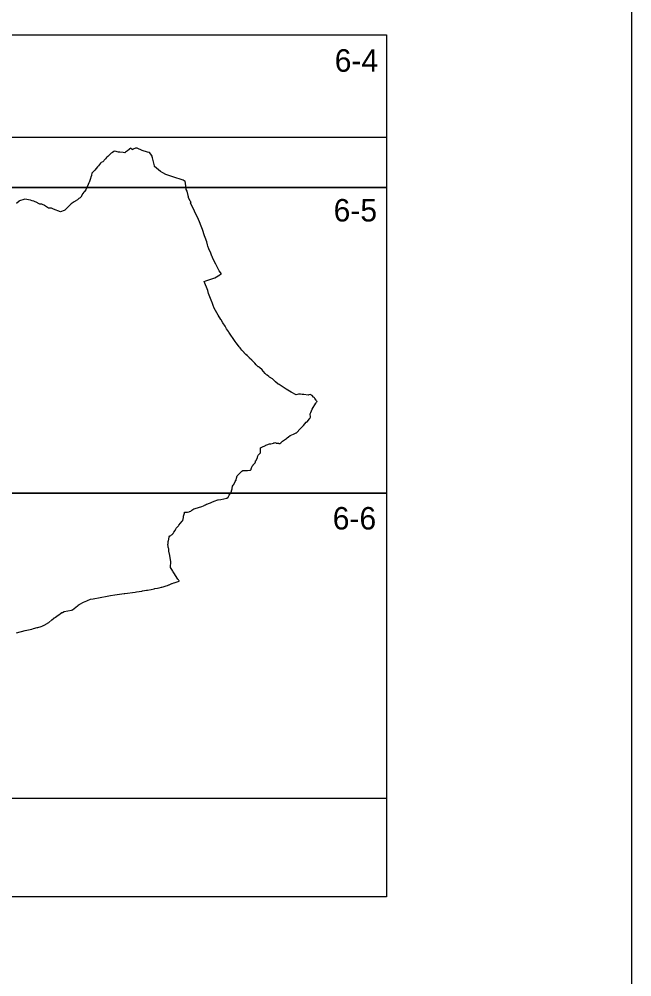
# Model space of a CAD drawing. Extents: x -447352 to -425530, y -1135906 to -1125104.
# Drawn here: x -443174.5 to -442923.9, y -1126663.9 to -1126271.9 of the extents above; entities that cross this region are included whole.
import ezdxf

# ---------------------------------------------------------------- set-up
doc = ezdxf.new("R2010")
doc.units = 0
for name, color, linetype in [('Vrstva 1', 7, 'Continuous'), ('Vrstva 10', 7, 'Continuous'), ('Vrstva 4', 7, 'Continuous')]:
    doc.layers.add(name, color=color, linetype=linetype)

msp = doc.modelspace()

# ---------------------------------------------------------------- linework, layer by layer
at = {"layer": 'Vrstva 1'}
msp.add_lwpolyline([(-444408.89, -1126016.81), (-444408.89, -1127066.81), (-442923.89, -1127066.81), (-442923.89, -1126016.81)], close=True, dxfattribs=at)
msp.add_lwpolyline([(-443175.6, -1126523.09), (-443172.06, -1126522.22), (-443169.29, -1126521.55), (-443168.62, -1126521.34), (-443167.13, -1126520.98), (-443166.92, -1126520.92), (-443165.49, -1126520.53), (-443164.89, -1126520.27), (-443164.67, -1126520.17), (-443164.51, -1126520.11), (-443163.69, -1126519.66), (-443163.63, -1126519.62), (-443162.32, -1126518.84), (-443161.17, -1126517.79), (-443160.52, -1126517.29), (-443160.39, -1126517.18), (-443160.37, -1126517.17), (-443160.21, -1126517.04), (-443160.06, -1126516.94), (-443159.26, -1126516.38), (-443159.2, -1126516.34), (-443159.13, -1126516.29), (-443158.62, -1126515.94), (-443158.25, -1126515.68), (-443157.59, -1126515.22), (-443157, -1126514.81), (-443156.84, -1126514.84), (-443156.83, -1126514.84), (-443156.81, -1126514.82), (-443156.08, -1126514.43), (-443153.12, -1126513.85), (-443152.7, -1126513.7), (-443150.67, -1126512.07), (-443150.2, -1126511.73), (-443150.17, -1126511.71), (-443149.81, -1126511.45), (-443149.63, -1126511.33), (-443148.24, -1126510.63), (-443146.83, -1126509.99), (-443146.53, -1126509.84), (-443145.27, -1126509.38), (-443144.27, -1126509.13), (-443138.56, -1126508.07), (-443137.14, -1126507.81), (-443135.43, -1126507.56), (-443131.56, -1126506.99), (-443131.32, -1126506.96), (-443127.02, -1126506.44), (-443126.49, -1126506.38), (-443124.34, -1126506.02), (-443124.02, -1126505.97), (-443122.36, -1126505.7), (-443121.96, -1126505.63), (-443120.55, -1126505.34), (-443119.26, -1126505.07), (-443119.05, -1126505.03), (-443117.88, -1126504.8), (-443117.21, -1126504.67), (-443117.19, -1126504.67), (-443116.28, -1126504.46), (-443116.21, -1126504.44), (-443115.56, -1126504.28), (-443115.21, -1126504.17), (-443114.32, -1126503.88), (-443113.88, -1126503.73), (-443113.23, -1126503.49), (-443113.11, -1126503.45), (-443112.02, -1126502.96), (-443112.02, -1126502.96), (-443111.9, -1126502.92), (-443111.25, -1126502.69), (-443111.16, -1126502.66), (-443110.73, -1126502.5), (-443109.07, -1126501.92), (-443109.09, -1126501.87), (-443109.2, -1126501.7), (-443109.36, -1126501.47), (-443109.58, -1126501.15), (-443111.28, -1126498.51), (-443111.49, -1126498.16), (-443111.66, -1126497.89), (-443112.1, -1126497.18), (-443112.63, -1126496.33), (-443112.47, -1126493.97), (-443112.46, -1126493.88), (-443112.85, -1126491.58), (-443112.85, -1126491.56), (-443112.86, -1126491.54), (-443112.86, -1126491.54), (-443112.86, -1126491.51), (-443113.27, -1126489.68), (-443113.28, -1126489.49), (-443113.34, -1126488.69), (-443113.44, -1126488.41), (-443113.45, -1126488.39), (-443113.56, -1126488.17), (-443113.6, -1126488.09), (-443113.61, -1126487.71), (-443113.64, -1126487.01), (-443113.59, -1126486.52), (-443113.59, -1126486.5), (-443113.5, -1126485.64), (-443113.48, -1126485.53), (-443113.19, -1126483.89), (-443113.11, -1126483.81), (-443112.81, -1126483.47), (-443112.75, -1126483.4), (-443112.49, -1126483.28), (-443112.43, -1126483.22), (-443112.17, -1126483.02), (-443111.94, -1126482.84), (-443111.73, -1126482.68), (-443111.67, -1126482.64), (-443111.59, -1126482.51), (-443111.51, -1126482.39), (-443111.4, -1126482.22), (-443111.18, -1126481.89), (-443110.76, -1126481.24), (-443110.63, -1126480.99), (-443110.62, -1126480.98), (-443110.48, -1126480.69), (-443110.43, -1126480.6), (-443110.25, -1126480.27), (-443110.11, -1126480.12), (-443109.81, -1126479.81), (-443109.64, -1126479.63), (-443109.36, -1126479.28), (-443109.23, -1126479.11), (-443108.54, -1126478.26), (-443107.88, -1126477.45), (-443107.59, -1126477.09), (-443107.35, -1126475.92), (-443107.29, -1126475.69), (-443107.22, -1126475.41), (-443106.9, -1126474.1), (-443106.82, -1126473.82), (-443106.82, -1126473.79), (-443106.8, -1126473.74), (-443106.64, -1126473.73), (-443106.62, -1126473.73), (-443106.38, -1126473.73), (-443105.69, -1126473.71), (-443105.68, -1126473.71), (-443105.65, -1126473.71), (-443104.97, -1126473.53), (-443104.77, -1126473.47), (-443104.35, -1126473.36), (-443104.33, -1126473.35), (-443104.27, -1126473.29), (-443103.97, -1126473.01), (-443103.85, -1126472.93), (-443103.51, -1126472.67), (-443103.09, -1126472.35), (-443103.02, -1126472.33), (-443102.46, -1126472.17), (-443099.76, -1126471.41), (-443099.17, -1126471.14), (-443098.84, -1126470.98), (-443098.79, -1126470.96), (-443098.69, -1126470.91), (-443098.33, -1126470.73), (-443098.28, -1126470.71), (-443098.25, -1126470.69), (-443098.24, -1126470.69), (-443098.21, -1126470.67), (-443097.9, -1126470.52), (-443097.84, -1126470.48), (-443097.73, -1126470.43), (-443096.65, -1126470.1), (-443096.22, -1126469.92), (-443095.7, -1126469.7), (-443094.69, -1126469.29), (-443093.27, -1126468.66), (-443093.13, -1126468.65), (-443092, -1126468.6), (-443089.6, -1126468.04), (-443089.07, -1126467.64), (-443089, -1126467.52), (-443088.91, -1126467.34), (-443088.65, -1126466.83), (-443088.3, -1126466.4), (-443088.28, -1126466.37), (-443088.07, -1126466.08), (-443087.96, -1126465.92), (-443087.95, -1126465.91), (-443087.41, -1126464.13), (-443087.4, -1126464.1), (-443087.2, -1126463.15), (-443086.94, -1126462.69), (-443086.75, -1126462.36), (-443086.2, -1126461.24), (-443085.82, -1126460.73), (-443085.79, -1126460.6), (-443085.72, -1126460.3), (-443085.69, -1126460.16), (-443085.63, -1126459.91), (-443085.61, -1126459.81), (-443085.29, -1126458.8), (-443085.28, -1126458.79), (-443084.99, -1126458.51), (-443084.33, -1126457.88), (-443084.28, -1126457.83), (-443083.81, -1126457.35), (-443083.55, -1126457.09), (-443083.45, -1126456.98), (-443083.08, -1126456.66), (-443083.04, -1126456.66), (-443083.03, -1126456.66), (-443082.62, -1126456.65), (-443082.45, -1126456.66), (-443081.82, -1126456.68), (-443081.11, -1126456.68), (-443080.14, -1126456.59), (-443080.11, -1126456.59), (-443079.86, -1126456.56), (-443079.64, -1126456.2), (-443079.59, -1126456.07), (-443079.57, -1126456.02), (-443079.55, -1126455.96), (-443079.19, -1126454.94), (-443079.05, -1126454.77), (-443078.95, -1126454.66), (-443078.91, -1126454.62), (-443078.85, -1126454.54), (-443078.73, -1126454.41), (-443078.46, -1126454.09), (-443078.37, -1126453.99), (-443078.27, -1126453.87), (-443077.93, -1126453.48), (-443077.86, -1126453.09), (-443077.8, -1126452.78), (-443077.73, -1126452.65), (-443077.18, -1126451.73), (-443077.07, -1126451.34), (-443076.88, -1126450.64), (-443076.76, -1126450.35), (-443076.47, -1126450.08), (-443075.92, -1126449.57), (-443075.85, -1126449.51), (-443075.75, -1126447.4), (-443074.73, -1126446.91), (-443074.33, -1126446.7), (-443074.08, -1126446.57), (-443073.79, -1126446.41), (-443073.57, -1126446.33), (-443073.23, -1126446.2), (-443073.18, -1126446.19), (-443072.09, -1126445.78), (-443072.08, -1126445.78), (-443071.59, -1126445.72), (-443071.51, -1126445.7), (-443070.48, -1126445.44), (-443070.33, -1126445.4), (-443070.24, -1126445.37), (-443070.07, -1126445.32), (-443069.54, -1126445.15), (-443069.54, -1126445.15), (-443069.53, -1126445.16), (-443069.53, -1126445.16), (-443069.5, -1126445.22), (-443069.37, -1126445.44), (-443068.49, -1126445.54), (-443068.29, -1126445.56), (-443067.93, -1126445.6), (-443067.84, -1126445.56), (-443067.41, -1126445.38), (-443066.76, -1126444.67), (-443065.12, -1126443.51), (-443065.03, -1126443.44), (-443064.86, -1126443.33), (-443064.35, -1126442.91), (-443063.6, -1126442.31), (-443062.33, -1126441.74), (-443061.71, -1126441.47), (-443061.17, -1126441.23), (-443061.11, -1126441.2), (-443059.46, -1126439.53), (-443058.62, -1126438.64), (-443058.26, -1126438.26), (-443057.07, -1126436.9), (-443056.47, -1126436.44), (-443056.42, -1126436.4), (-443055.58, -1126435.39), (-443055.38, -1126434.82), (-443055.47, -1126433.49), (-443055.25, -1126433), (-443054.61, -1126431.55), (-443053.15, -1126429.07), (-443053.12, -1126429.02), (-443053.12, -1126429.02), (-443053.1, -1126428.99), (-443053.07, -1126428.95), (-443052.92, -1126428.76), (-443052.66, -1126428.42), (-443052.92, -1126428.12), (-443053.06, -1126427.9), (-443053.53, -1126427.16), (-443053.73, -1126426.97), (-443053.88, -1126426.81), (-443054.07, -1126426.61), (-443054.65, -1126426.04), (-443055.5, -1126425.57), (-443055.95, -1126425.75), (-443056.28, -1126425.87), (-443058.03, -1126425.6), (-443058.64, -1126425.51), (-443058.78, -1126425.5), (-443059.37, -1126425.48), (-443059.75, -1126425.43), (-443059.91, -1126425.4), (-443059.95, -1126425.4), (-443059.98, -1126425.39), (-443059.98, -1126425.39), (-443060.01, -1126425.4), (-443060.11, -1126425.43), (-443060.24, -1126425.46), (-443061.14, -1126425.7), (-443061.21, -1126425.67), (-443063.28, -1126424.63), (-443065.3, -1126423.35), (-443068.21, -1126421.53), (-443068.37, -1126421.39), (-443068.41, -1126421.36), (-443068.5, -1126421.28), (-443069.64, -1126420.35), (-443070.79, -1126419.3), (-443070.9, -1126419.2), (-443072.11, -1126418.44), (-443072.39, -1126418.21), (-443073.02, -1126417.71), (-443073.33, -1126417.47), (-443073.83, -1126416.94), (-443074.55, -1126416.18), (-443074.7, -1126416.02), (-443075.16, -1126415.53), (-443076.13, -1126414.5), (-443076.33, -1126414.39), (-443076.33, -1126414.39), (-443076.51, -1126414.3), (-443076.71, -1126414.2), (-443077.54, -1126413.37), (-443078.17, -1126412.74), (-443079.35, -1126411.57), (-443080.28, -1126410.63), (-443080.44, -1126410.48), (-443080.88, -1126410.03), (-443081.12, -1126409.79), (-443081.21, -1126409.7), (-443081.25, -1126409.66), (-443081.77, -1126409.14), (-443082.41, -1126408.49), (-443082.49, -1126408.41), (-443082.51, -1126408.39), (-443082.66, -1126408.24), (-443083.49, -1126407.4), (-443083.87, -1126406.9), (-443084.15, -1126406.53), (-443084.47, -1126406.1), (-443084.83, -1126405.62), (-443085.78, -1126404.36), (-443086.15, -1126403.82), (-443088.69, -1126400.08), (-443088.86, -1126399.82), (-443089.63, -1126398.63), (-443090.3, -1126397.62), (-443091.14, -1126396.29), (-443091.94, -1126395.02), (-443092.02, -1126394.89), (-443093.11, -1126393.04), (-443094.79, -1126390.19), (-443094.79, -1126390.18), (-443094.79, -1126390.18), (-443094.8, -1126390.18), (-443095.13, -1126389.2), (-443095.58, -1126387.9), (-443095.64, -1126387.7), (-443097.02, -1126384.19), (-443097.31, -1126382.94), (-443098.79, -1126379.26), (-443098.16, -1126379.06), (-443094.44, -1126377.82), (-443092.47, -1126376.6), (-443092.29, -1126376.49), (-443092.23, -1126376.45), (-443092.03, -1126376.33), (-443091.76, -1126376.16), (-443092.68, -1126374.97), (-443094.09, -1126372.19), (-443094.84, -1126370.72), (-443095.37, -1126369.56), (-443095.39, -1126369.52), (-443095.45, -1126369.39), (-443095.46, -1126369.36), (-443095.48, -1126369.33), (-443095.52, -1126369.24), (-443095.85, -1126368.51), (-443096.17, -1126367.72), (-443096.88, -1126365.95), (-443097.29, -1126364.91), (-443097.44, -1126364.28), (-443097.7, -1126363.15), (-443098.44, -1126361.26), (-443098.64, -1126360.66), (-443099.58, -1126358.03), (-443099.85, -1126357.31), (-443101.04, -1126354.22), (-443101.11, -1126354.04), (-443101.14, -1126353.96), (-443104.49, -1126347.15), (-443104.18, -1126347.01), (-443104.16, -1126347), (-443104.26, -1126346.83), (-443104.34, -1126346.73), (-443104.51, -1126346.5), (-443104.57, -1126346.42), (-443105.18, -1126344.94), (-443105.23, -1126344.65), (-443105.33, -1126344.19), (-443105.34, -1126344.13), (-443105.85, -1126342.29), (-443106.15, -1126341.66), (-443106.16, -1126341.58), (-443106.2, -1126341.22), (-443106.34, -1126340.13), (-443106.62, -1126338.29), (-443106.68, -1126338.27), (-443106.98, -1126338.17), (-443107.36, -1126337.91), (-443107.37, -1126337.91), (-443111.67, -1126336.5), (-443114.46, -1126335.52), (-443115.77, -1126334.9), (-443116.74, -1126334.34), (-443117.46, -1126333.56), (-443119.14, -1126332.29), (-443119.2, -1126331.99), (-443119.78, -1126329.29), (-443119.93, -1126328.75), (-443120.11, -1126328.24), (-443120.16, -1126328.08), (-443120.41, -1126327.56), (-443120.66, -1126327.25), (-443121.24, -1126326.56), (-443121.99, -1126326.35), (-443124.17, -1126325.69), (-443126.26, -1126324.73), (-443126.88, -1126324.73), (-443127.83, -1126325.1), (-443127.96, -1126325.19), (-443128.03, -1126325.24), (-443128.17, -1126325.34), (-443128.21, -1126325.37), (-443128.23, -1126325.35), (-443128.44, -1126325.1), (-443128.69, -1126324.82), (-443128.77, -1126324.72), (-443128.86, -1126324.76), (-443129.37, -1126325.15), (-443129.56, -1126325.3), (-443130.23, -1126325.82), (-443130.98, -1126326.38), (-443131.32, -1126326.6), (-443131.91, -1126326.56), (-443133.39, -1126326.41), (-443133.85, -1126326.32), (-443135.44, -1126326), (-443135.74, -1126326.11), (-443136.3, -1126326.46), (-443136.85, -1126326.78), (-443137.34, -1126327.24), (-443137.87, -1126327.73), (-443138.27, -1126328.12), (-443138.28, -1126328.13), (-443138.61, -1126328.47), (-443138.74, -1126328.61), (-443139.25, -1126329.16), (-443139.7, -1126329.71), (-443139.86, -1126329.9), (-443140.22, -1126330.33), (-443140.96, -1126330.66), (-443140.98, -1126330.66), (-443141.18, -1126330.91), (-443142.04, -1126331.93), (-443142.42, -1126332.38), (-443143.55, -1126333.74), (-443143.56, -1126333.75), (-443144.8, -1126334.92), (-443144.92, -1126335.76), (-443144.97, -1126336.13), (-443145.01, -1126336.23), (-443145.49, -1126337.58), (-443145.93, -1126338.82), (-443145.96, -1126338.9), (-443146.26, -1126339.59), (-443147.19, -1126341.77), (-443147.21, -1126341.78), (-443147.78, -1126342.46), (-443148.08, -1126342.81), (-443148.08, -1126342.82), (-443148.42, -1126343.36), (-443149.29, -1126344.75), (-443149.38, -1126344.89), (-443149.55, -1126345.02), (-443150.08, -1126345.41), (-443150.69, -1126345.86), (-443150.69, -1126345.86), (-443151.66, -1126346.49), (-443151.79, -1126346.58), (-443151.97, -1126346.7), (-443153.27, -1126347.56), (-443153.28, -1126347.57), (-443153.54, -1126347.83), (-443153.66, -1126347.95), (-443153.88, -1126348.18), (-443154.16, -1126348.46), (-443154.73, -1126349.03), (-443155.89, -1126350.19), (-443156.09, -1126350.27), (-443157.59, -1126350.84), (-443160.4, -1126349.72), (-443160.4, -1126349.73), (-443160.41, -1126349.75), (-443161.32, -1126349.37), (-443161.63, -1126349.24), (-443161.65, -1126349.24), (-443162.04, -1126349.24), (-443162.52, -1126349.24), (-443164.08, -1126348.25), (-443164.34, -1126348.12), (-443164.63, -1126347.96), (-443164.69, -1126347.93), (-443164.73, -1126347.91), (-443165.27, -1126347.68), (-443165.32, -1126347.68), (-443165.33, -1126347.68), (-443165.48, -1126347.67), (-443165.6, -1126347.66), (-443165.91, -1126347.64), (-443165.93, -1126347.64), (-443165.93, -1126347.64), (-443166.04, -1126347.6), (-443166.28, -1126347.5), (-443166.88, -1126347.25), (-443167.04, -1126347.18), (-443168.56, -1126346.45), (-443169.18, -1126346.27), (-443169.85, -1126346.07), (-443172.17, -1126345.64), (-443172.18, -1126345.64), (-443172.58, -1126345.75), (-443174.32, -1126346.33), (-443174.45, -1126346.44), (-443175.66, -1126347.4)], dxfattribs=at)
at = {"layer": 'Vrstva 10'}
msp.add_lwpolyline([(-443024.3, -1126320.23), (-443024.3, -1126631.21), (-443357.17, -1126631.21), (-443357.17, -1126465.91), (-443336.8, -1126465.91), (-443336.8, -1126340.91), (-443336.8, -1126320.23), (-443024.3, -1126320.23)], dxfattribs=at)
at = {"layer": 'Vrstva 4'}
msp.add_line((-443336.8, -1126278.41), (-443024.3, -1126278.41), dxfattribs=at)
msp.add_lwpolyline([(-443024.3, -1126278.41), (-443024.3, -1126340.91), (-443180.55, -1126340.91), (-443180.55, -1126278.41)], dxfattribs=at)
for points in [[(-443024.3, -1126340.91), (-443024.3, -1126465.91), (-443180.55, -1126465.91), (-443180.55, -1126340.91)], [(-443024.3, -1126465.91), (-443024.3, -1126590.91), (-443180.55, -1126590.91), (-443180.55, -1126465.91)]]:
    msp.add_lwpolyline(points, close=True, dxfattribs=at)

# ---------------------------------------------------------------- texts
at = {"layer": 'Vrstva 1'}
for s, p in [('6-4', (-443045.43, -1126293.46)), ('6-5', (-443045.88, -1126354.75)), ('6-6', (-443046.25, -1126480.82))]:
    msp.add_text(s, height=9.2, dxfattribs=at).set_placement(p)

doc.saveas('drawing.dxf')
